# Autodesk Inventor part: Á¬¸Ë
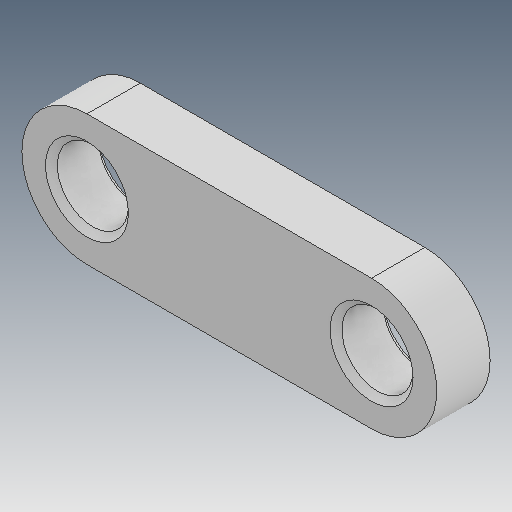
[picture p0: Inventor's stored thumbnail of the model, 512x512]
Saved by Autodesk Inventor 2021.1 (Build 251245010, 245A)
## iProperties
Created: 2019-04
Part Number: Á¬¸Ë
Material: Ogólny
Document SubType Name: Modeling
Designer: user
Density: 1 g/cm^3
Appearance: Domyślna
Author: user
Revision Number: ÈÎºÎ
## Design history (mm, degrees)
feature "ÊäÈë1"
node "Bryła1"
